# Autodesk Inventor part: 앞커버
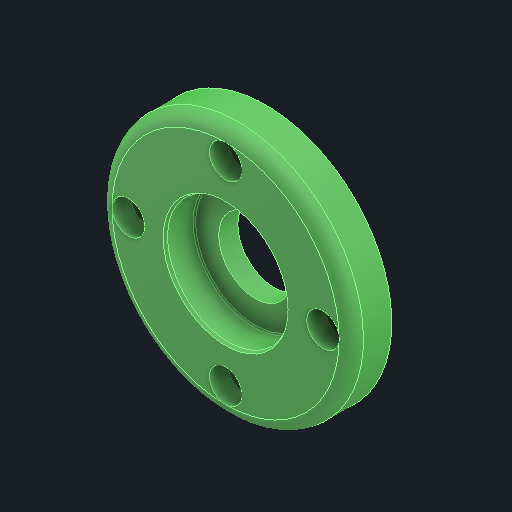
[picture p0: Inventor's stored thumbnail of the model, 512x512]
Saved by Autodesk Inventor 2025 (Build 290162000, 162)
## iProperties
Created: 2025-08
Part Number: 앞커버
Material: 알루미늄 6061
Document SubType Name: Modeling
Designer: infra002
Density: 2.71 g/cm^3
Appearance: 기본값
Author: jhkim
Sending System: Autodesk Inventor 2026
Preprocessor: ST-DEVELOPER v20.1
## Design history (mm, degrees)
feature "솔리드1"
node "솔리드2"
